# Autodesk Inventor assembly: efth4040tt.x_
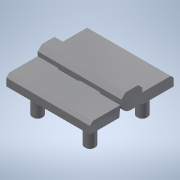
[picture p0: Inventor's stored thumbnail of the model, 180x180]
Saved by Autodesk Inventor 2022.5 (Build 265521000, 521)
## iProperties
Part Number: efth4040tt.x_
Material: 一般
Document SubType Name: Assembly
Designer: ImaoCorp
Sending System: SOLIDWORKS 2017-2017317
MC: AMD64
MC_MODEL: Intel64 Family 6 Model 60 Stepping 3, GenuineIntel
OS: Windows_NT
FRU: Parasolid Version 29.0, build 201,  4-17-2017
FORMAT: text
GUISE: transmit
KEY: efth4040tt
FILE: efth4040tt.x_t
DATE: Mon May 13 14:22:19 2019
Author: ImaoCorp
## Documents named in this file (4)
- X:\14_SW2022-Inv2022\00_全2023-1023新製品(TCC)まで\e\efth4040tt\EFTH4040TT.iam
- X:\14_SW2022-Inv2022\00_全2023-1023新製品(TCC)まで\e\efth4040tt\efth4040tt_01.ipt
- X:\14_SW2022-Inv2022\00_全2023-1023新製品(TCC)まで\e\efth4040tt\efth4040tt_02.ipt
- X:\14_SW2022-Inv2022\00_全2023-1023新製品(TCC)まで\e\efth4040tt\efth4040tt_03.ipt
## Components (3 placed, 3 different names)
1. efth4040tt_01
2. efth4040tt_02
3. efth4040tt_03
